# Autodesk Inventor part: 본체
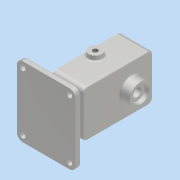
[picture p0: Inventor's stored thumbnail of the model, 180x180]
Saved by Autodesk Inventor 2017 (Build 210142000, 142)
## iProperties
Part Number: 본체
Material: 알루미늄 6061
Document SubType Name: Modeling
Designer: MRC
Density: 2.7 g/cm^3
Appearance: 알루미늄 - 평지
Mass: 1472.61 g
Surface Area: 819.603 cm^2
Volume: 545.411 cm^3
Author: MRC
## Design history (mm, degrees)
sketch "스케치1"
  geometry: L1 (-14, 60)-(39, 60); L2 (39, 60)-(39, -60); L3 (39, -60)-(-14, -60); L4 (-14, -60)-(-14, 60); 1 further point
  constraints: 8 end point, 2 parallel, 1 horizontal, 1 perpendicular
  dimensions: "d0" = 14 distance from line of point (0, 0) L4; "d1" = 53 distance between parallel lines of L2 L4; "d2" = 120 distance between parallel lines of L3 L1; "d3" = 60 distance from line of point (0, 0) L1
extrude "돌출1" new body sketch "스케치1" stored distance "d4" = 80; taper "d5" = 0 deg
sketch "스케치2"
  geometry: L1 (-80, 0)-(-80, 120) reference; L2 (-40, 82)-(-40, 38); L3 (-64, 82)-(-64, 38); L4 (-16, 38)-(-16, 82); A1 r 24 centre (-40, 82) between (-16, 82) and (-64, 82); A2 r 24 centre (-40, 38) between (-64, 38) and (-16, 38); 2 further points
  constraints: 8 end point, 4 point on circle, 4 tangent, 2 centre point, 2 coincident, 2 parallel, 1 midpoint
  dimensions: "d6" = 24 radius of A2; "d8" = 44 distance of L2.start L2.end
extrude "돌출2" cut sketch "스케치2" distance "d9" = 29; taper "d10" = 0 deg
sketch "스케치3"
  geometry: C1 r 19 at (40, 82); C2 r 14 at (40, 82); A1 r 24 centre (40, 82) between (64, 82) and (16, 82) reference; 1 further point
  constraints: 2 centre point, 2 coincident
  dimensions: "d11" = 38 diameter of C1; "d12" = 28 diameter of C2
extrude "돌출3" join sketch "스케치3" distance "d13" = 17; taper "d14" = 0 deg
hole "구멍2" diameter "d28" = 25; stored, may be unused: countersink angle "d32" = 90 deg, drill point angle "d34" = 0 deg; dims "d29" = 6, "d30" = 25, "d31" = 15, "d33" = 15, "d35" = 10, "d36" = 10
sketch "스케치4"
  geometry: L1 (-44, -80)-(56, -80); L2 (56, -80)-(56, -90); L3 (56, -90)-(-44, -90); L4 (-44, -90)-(-44, -80); L5 (39, 60)-(-14, 60) reference; L6 (56, 3)-(56, 41) reference; 1 further point
  constraints: 8 end point, 2 parallel, 1 horizontal, 1 perpendicular, 1 vertical alignment
  dimensions: "d39" = 150 distance between parallel lines of L5 L3; "d40" = 10 distance between parallel lines of L3 L1; "d41" = 100 distance between parallel lines of L2 L4
extrude "돌출5" join sketch "스케치4" stored distance "d42" = 120; taper "d43" = 0 deg
fillet "모깎기1" dims "d64" = 9
sketch "스케치6"
  geometry: A1 r 9 centre (9, 102) between (9, 111) and (0, 102) reference; 2 further points
  constraints: 1 coincident
hole "구멍3" sketch "스케치6" at (9, 102) diameter "d65" = 4.134; stored, may be unused: countersink angle "d69" = 90 deg, drill point angle "d71" = 118 deg; dims "d66" = 10, "d67" = 25, "d68" = 15, "d70" = 12
node "작업 평면1"
sketch "스케치7"
  geometry: C1 r 11 at (0, 0); 1 further point
  constraints: 1 centre point, 1 coincident
  dimensions: "d79" = 22 diameter of C1
extrude "돌출7" join sketch "스케치7" stored distance "d80" = 48; taper "d81" = 0 deg
hole "구멍4" diameter "d84" = 8.376; stored, may be unused: countersink angle "d88" = 90 deg, drill point angle "d90" = 0 deg; dims "d82" = 10, "d83" = 10, "d85" = 27, "d86" = 25, "d87" = 15, "d89" = 27
fillet "모깎기2" dims "d91" = 10
sketch "스케치8"
  geometry: C1 r 4.5 at (0, -10); C2 r 4.5 at (0, -110); C3 r 4.5 at (80, -110); C4 r 4.5 at (80, -10); A1 r 10 centre (80, -10) between (90, -10) and (80, 0) reference; A2 r 10 centre (0, -10) between (0, 0) and (-10, -10) reference; A3 r 10 centre (0, -110) between (-10, -110) and (0, -120) reference; A4 r 10 centre (80, -110) between (80, -120) and (90, -110) reference; 1 further point
  constraints: 4 centre point, 4 coincident, 3 equal radius
  dimensions: "d92" = 9 diameter of C2
extrude "돌출8" cut sketch "스케치8" distance "d93" = 48; taper "d94" = 0 deg
fillet "모깎기3" dims "d95" = 3
sketch "스케치5"
  geometry: L1 (-14, -80)-(-2.453, -60); L2 (39, -80)-(27.453, -60); L3 (-44, -80)-(56, -80) reference; L4 (56, -80)-(56, -90) reference; L5 (-14, -80)-(39, -80); L6 (39, -60)-(-14, -60) reference; L7 (27.453, -60)-(-2.453, -60); 1 further point
  constraints: 8 end point, 4 point on line, 1 collinear
  dimensions: "d44" = 53 distance of L1.start L2.start; "d45" = 17 distance from line of L2.start L4; "d46" = 60 deg angle of L3 L1; "d47" = 60 deg angle of L3 L2
extrude "돌출9" join sketch "스케치5" stored distance "d96" = 48; taper "d97" = 0 deg
fillet "모깎기4" dims "d98" = 3
fillet "모깎기5" dims "d99" = 3
fillet "모깎기6" dims "d100" = 3
fillet "모깎기7" dims "d101" = 3
extrude "돌출10" join sketch "스케치3" stored distance "d110" = 48; taper "d111" = 0 deg
hole "구멍1" diameter "d19" = 17; stored, may be unused: countersink angle "d23" = 90 deg, drill point angle "d25" = 0 deg; dims "d20" = 6, "d21" = 25, "d22" = 15, "d24" = 50, "d112" = 10, "d113" = 10
sketch "스케치10"
  geometry: C1 r 8.5 at (0, 0) reference; C2 r 19 at (0, 0) reference; C3 r 14 at (0, 0); 1 further point
  constraints: 1 centre point, 1 coincident
  dimensions: "d114" = 28 diameter of C3
extrude "돌출11" cut sketch "스케치10" distance "d115" = 7.3; taper "d116" = 0 deg
chamfer "모따기2" distance "d117" = 0.7; stored, may be unused: second distance "d118" = 2, angle "d119" = 30 deg
fillet "모깎기9" dims "d120" = 0.5
chamfer "모따기3" distance "d121" = 1; stored, may be unused: second distance "d122" = 2, angle "d123" = 30 deg
sketch "스케치9"
  geometry: L1 (80, 117)-(0, 117) reference; L2 (-10, 107)-(-10, 7) reference; 2 further points
  constraints: 1 other
  dimensions: "d106" = 60 distance from line of L1 point (0, 57); "d107" = 10 distance from line of L2 point (0, 57)
feature "엠보싱1" sketch "스케치9" dims "d0" = 14, "d1" = 53, "d2" = 120, "d3" = 60, "d108" = 1, "d109" = 0
node "솔리드1"
pattern_linear "직사각형 패턴1" dims "d74" = 62, "d77" = 29
mirror "미러1"
mirror "미러2"
other parameters: "d78" = 48
